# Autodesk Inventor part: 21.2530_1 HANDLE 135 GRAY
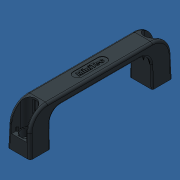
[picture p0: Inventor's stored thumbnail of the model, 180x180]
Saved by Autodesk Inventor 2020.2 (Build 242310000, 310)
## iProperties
Created: 2016-08
Part Number: 21.2530_1 HANDLE 135 GRAY
Material: PA 6.6
Document SubType Name: Modeling
Designer: MuellerJ
Mass: 37.3904 g
Surface Area: 243.908 cm^2
Volume: 35.274 cm^3
Density: 1.06 g/cm^3
Appearance: RAL 7012 Basaltgrau
Description: Handgriff 135 Einzelteil grau
Beschreibung: Handgriff 135 Einzelteil grau
Bezeichnung: Handgriff 135 Einzelteil grau
Artikelnr: 212530/3
Klassifizierung: Griffe,Schlösser,Anschläge
Lieferantennr: 72401
Zeichnungsnr: 21-2530-3FZ.003
MiniTec_ID: 212530/3
Teileart: K
Lieferant: MiniTec
Author: MuellerJ
Title: Handgriff 135 Einzelteil grau
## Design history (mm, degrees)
feature "1DE00"
feature "Körper verschieben1"
node "Volumenkörper1"
other parameters: "d0" = 33.883, "d1" = -86.332, "d2" = 39.97
